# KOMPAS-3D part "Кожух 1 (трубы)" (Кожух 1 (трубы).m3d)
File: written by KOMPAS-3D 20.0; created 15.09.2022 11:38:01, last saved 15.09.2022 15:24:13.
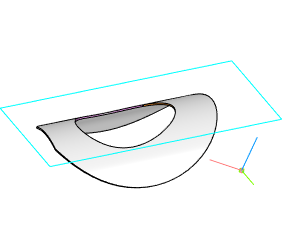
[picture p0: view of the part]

Document properties: Полное имя файла: D:\YAKOVLEV\ПРОЕКТЫ\ДЦ-2. ДП-7 Газопровод Окожушивание\ПРОБА Соединение труб. Окожушивание\Кожух 1 (трубы).m3d

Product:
- Part/product: Кожух 1 (трубы)
    Материал: Сталь 45  ГОСТ 1050-2013 (density 7810 kg/m3)
    Масса: 419.401

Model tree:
1. Эскиз:1  (with: Обечайка:1)  (labels: Кожух 1 (трубы))
2. Обечайка:1  (labels: Кожух 1 (трубы))
     Расстояние 1 = -2450; Смещение 1 = -50; Толщина листового тела = 20
3. Сгиб(1) - Обечайка:1
     Радиус сгиба = 980; Коэффициент = 0.4; Величина сгиба = 10; Зазор = 1
4. Касательная плоскость:1  (with: Обечайка:1)
5. Эскиз:2  (with: Обечайка:1)  (labels: Кожух 1 (трубы))
6. Вырез в листовом теле:2
     Глубина выреза = 2400
7. Разогнуть:1  (with: Обечайка:1)
8. Эскиз:3  (with: Обечайка:1, Вырез в листовом теле:2)
9. Вырез в листовом теле:3
     Глубина выреза = 1000
10. Эскиз:4  (with: Обечайка:1, Вырез в листовом теле:2, Вырез в листовом теле:3)
11. Вырез в листовом теле:4
     Глубина выреза = 1000
12. Эскиз:5  (with: Обечайка:1, Вырез в листовом теле:3, Вырез в листовом теле:4)
13. Вырез в листовом теле:5
     Глубина выреза = 10
14. Фаска:1  (with: Вырез в листовом теле:2, Вырез в листовом теле:3, Вырез в листовом теле:4)
     Угол = 45; Длина 1 = 3; Длина 2 = 3
15. Согнуть:1  (with: Обечайка:1)
16. Развертка  (labels: Сталь 45  ГОСТ 1050-2013)

Expressions: v140*2
Referenced files in D:\YAKOVLEV\ПРОЕКТЫ\ДЦ-2. ДП-7 Газопровод Окожушивание\ПРОБА Соединение труб. Окожушивание\: Соединение труб. Окожушивание -2.a3d
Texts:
  Соединение труб. Окожушивание\Труба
